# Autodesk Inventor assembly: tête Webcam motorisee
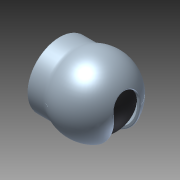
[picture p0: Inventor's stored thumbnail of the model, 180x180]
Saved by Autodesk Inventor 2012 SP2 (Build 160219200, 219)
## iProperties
Created: 2013-08
Part Number: tête Webcam motorisee
Document SubType Name: Assembly
Designer: hilarion
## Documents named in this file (3)
- L:\STI2D\Ressources eleves\ITEC\Tsti2d Fichot 2013-14\Webcam motorisee\tête Webcam motorisee.iam
- L:\STI2D\Ressources eleves\ITEC\Tsti2d Fichot 2013-14\Webcam motorisee\SE-Camera.iam
- L:\STI2D\Ressources eleves\ITEC\Tsti2d Fichot 2013-14\Webcam motorisee\SE-Coques.iam
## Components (2 placed, 2 different names)
1. SE-Camera:1 [sub-assembly]
2. SE-Coques:1 [sub-assembly]
